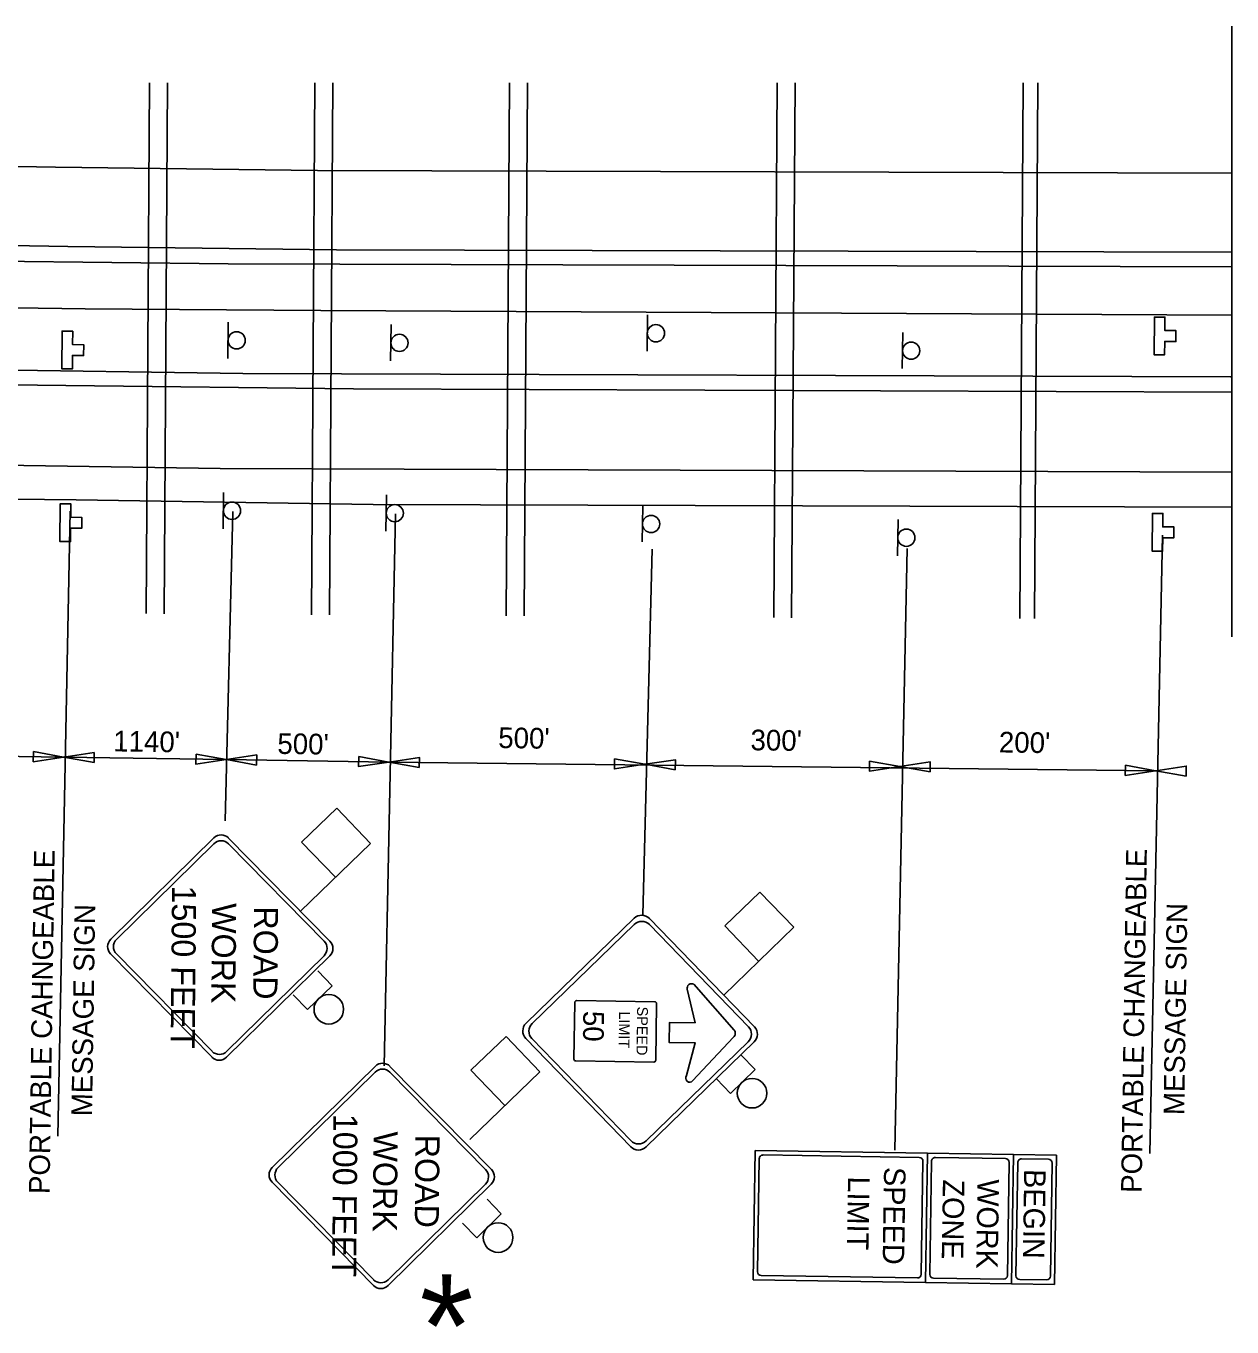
# Model space of a CAD drawing. Extents: x 2155255 to 2162649, y 140388 to 141878.
# Drawn here: x 2158635.8 to 2158985.8, y 141223.4 to 141600.8 of the extents above; entities that cross this region are included whole.
import ezdxf

# ---------------------------------------------------------------- set-up
doc = ezdxf.new("R2010")
doc.units = 0
for name, color, linetype in [('5', 7, 'Continuous'), ('Default', 7, 'Continuous'), ('PR_Dimensions', 7, 'Continuous'), ('PR_Dimensions_Phase4', 7, 'Continuous'), ('PR_Traffic_Control_Devices_Temp', 7, 'Continuous'), ('PR_Traffic_Control_Devices_Temp_Ph4', 7, 'Continuous'), ('SHT_Match_Lines', 7, 'Continuous'), ('T_PHASE_4', 7, 'Continuous'), ('TOPO_Asphalt', 7, 'Continuous')]:
    doc.layers.add(name, color=color, linetype=linetype)

# ---------------------------------------------------------------- blocks, each defined once
blk = doc.blocks.new('Arrowhd')
at = {"layer": 'Default'}
blk.add_lwpolyline([(0.318, -0.053), (0.318, 0.053), (0, 0)], close=True, dxfattribs=at)
blk = doc.blocks.new('PR-TCSIGN')
at = {"layer": 'Default'}
blk.add_line((17.8, 8.5), (-17.8, 8.5), dxfattribs=at)
blk.add_circle((0, 0), 8.47, dxfattribs=at)
blk = doc.blocks.new('FLSHFLAG')
at = {"layer": 'Default'}
for p, q in [((-1.202, 14.125), (0.838, 16.147)), ((0.838, 16.147), (4.9, 12.085)), ((0.819, 12.085), (-1.202, 14.125)), ((0.819, 12.085), (2.86, 14.106)), ((9.258, 14.004), (8.403, 13.149)), ((9.258, 14.004), (10.685, 12.576)), ((10.685, 12.576), (9.831, 11.722))]:
    blk.add_line(p, q, dxfattribs=at)
blk.add_circle((10.653, 13.836), 0.873, dxfattribs=at)
blk = doc.blocks.new('CS-13E')
at = {"layer": 'Default'}
for p, q in [((0, 2.54), (0, 0)), ((7.62, 2.54), (0, 2.54)), ((7.62, 0), (7.62, 2.54)), ((0.254, 2.064), (0.254, 0.476)), ((7.144, 2.286), (0.476, 2.286)), ((7.366, 0.476), (7.366, 2.064)), ((7.62, 0), (0, 0)), ((0.476, 0.254), (7.144, 0.254))]:
    blk.add_line(p, q, dxfattribs=at)
for centre, start, end in [((0.476, 2.064), 90, 180), ((7.144, 2.064), 0, 90), ((0.476, 0.476), 180, 270), ((7.144, 0.476), 270, 0)]:
    blk.add_arc(centre, 0.222, start, end, dxfattribs=at)
blk.add_text('BEGIN', height=1.27, dxfattribs=at).set_placement((0.847, 0.644))
blk = doc.blocks.new('R2-1E_2')
at = {"layer": 'Default'}
for p, q in [((7.62, 10.16), (0, 10.16)), ((0, 10.16), (0, 0)), ((7.62, 0), (7.62, 10.16)), ((0.254, 9.684), (0.254, 0.476)), ((7.144, 9.906), (0.476, 9.906)), ((7.366, 0.476), (7.366, 9.684)), ((0, 0), (7.62, 0)), ((0.476, 0.254), (7.144, 0.254))]:
    blk.add_line(p, q, dxfattribs=at)
for centre, start, end in [((0.476, 9.684), 90, 180), ((7.144, 9.684), 0, 90), ((0.476, 0.476), 180, 270), ((7.144, 0.476), 270, 0)]:
    blk.add_arc(centre, 0.222, start, end, dxfattribs=at)
for s, p in [('SPEED', (0.847, 7.62)), ('LIMIT', (1.439, 5.503))]:
    blk.add_text(s, height=1.27, dxfattribs=at).set_placement(p)
blk = doc.blocks.new('CS-14E')
at = {"layer": 'Default'}
for p, q in [((7.62, 2.54), (0, 2.54)), ((0, 2.54), (0, -2.54)), ((7.62, -2.54), (7.62, 2.54)), ((0.254, 2.064), (0.254, -2.064)), ((7.144, 2.286), (0.476, 2.286)), ((7.366, -2.064), (7.366, 2.064)), ((0.476, -2.286), (7.144, -2.286)), ((7.62, -2.54), (0, -2.54))]:
    blk.add_line(p, q, dxfattribs=at)
for centre, start, end in [((0.476, 2.064), 90, 180), ((7.144, 2.064), 0, 90), ((0.476, -2.064), 180, 270), ((7.144, -2.064), 270, 0)]:
    blk.add_arc(centre, 0.222, start, end, dxfattribs=at)
for s, p in [('WORK', (1.482, 0.444)), ('ZONE', (1.526, -1.598))]:
    blk.add_text(s, height=1.27, dxfattribs=at).set_placement(p)
blk = doc.blocks.new('W3-5_2')
at = {"layer": '5'}
for p, q in [((0.808, 7.633), (6.735, 13.56)), ((13.56, 7.633), (7.633, 13.56)), ((6.735, 0.808), (0.808, 6.735)), ((7.633, 0.808), (13.56, 6.735))]:
    blk.add_line(p, q, dxfattribs=at)
for centre, start, end in [((7.184, 13.111), 45, 135), ((1.257, 7.184), 135, 225), ((13.111, 7.184), 315, 45), ((7.184, 1.257), 225, 315)]:
    blk.add_arc(centre, 0.635, start, end, dxfattribs=at)
at = {"layer": 'Default'}
for p, q in [((0.448, 7.633), (6.735, 13.919)), ((13.919, 7.633), (7.633, 13.919)), ((6.95, 12.723), (4.277, 10.304)), ((9.984, 10.322), (7.366, 12.687)), ((5.352, 8.019), (5.352, 3.415)), ((8.797, 8.13), (5.464, 8.13)), ((8.908, 3.415), (8.908, 8.019)), ((6.735, 0.449), (0.448, 6.735)), ((7.633, 0.449), (13.919, 6.735)), ((5.464, 3.304), (8.797, 3.304))]:
    blk.add_line(p, q, dxfattribs=at)
for points in [[(4.277, 10.304), (6.95, 12.723)], [(7.366, 12.687), (9.984, 10.322)], [(4.584, 9.924), (6.553, 10.412), (6.553, 8.913), (7.745, 8.913), (7.745, 10.448), (9.677, 9.96)], [(9.677, 9.96), (7.745, 10.448), (7.745, 8.913), (6.553, 8.913), (6.553, 10.412), (4.584, 9.924)]]:
    blk.add_lwpolyline(points, dxfattribs=at)
for centre, radius, start, end in [((7.184, 13.47), 0.635, 45, 135), ((7.141, 12.512), 0.285, 37.91416, 132.14933), ((7.141, 12.512), 0.285, 37.91416, 132.14933), ((4.519, 10.186), 0.269, 154.09026, 283.9085), ((4.519, 10.186), 0.269, 154.09026, 283.9085), ((9.825, 10.146), 0.237, 231.34169, 47.91235), ((9.825, 10.146), 0.237, 231.34169, 47.91235), ((5.464, 8.019), 0.111, 90, 180), ((8.797, 8.019), 0.111, 0, 90), ((0.897, 7.184), 0.635, 135, 225), ((13.47, 7.184), 0.635, 315, 45), ((5.464, 3.415), 0.111, 180, 270), ((8.797, 3.415), 0.111, 270, 0), ((7.184, 0.898), 0.635, 225, 315)]:
    blk.add_arc(centre, radius, start, end, dxfattribs=at)
for s, p in [('SPEED', (5.649, 6.987)), ('LIMIT', (5.945, 5.929))]:
    blk.add_text(s, height=0.635, dxfattribs=at).set_placement(p)
blk = doc.blocks.new('Cw20-1_none')
at = {"layer": 'Default'}
for p, q in [((0.177, 3.005), (2.651, 5.48)), ((5.48, 3.005), (3.005, 5.48)), ((0.318, 3.005), (2.651, 5.339)), ((5.338, 3.005), (3.005, 5.339)), ((2.651, 0.177), (0.177, 2.652)), ((2.651, 0.318), (0.318, 2.652)), ((3.005, 0.177), (5.48, 2.652)), ((3.005, 0.318), (5.338, 2.652))]:
    blk.add_line(p, q, dxfattribs=at)
for centre, start, end in [((2.828, 5.303), 45, 135), ((2.828, 5.162), 45, 135), ((0.353, 2.828), 135, 225), ((0.495, 2.828), 135, 225), ((5.162, 2.828), 315, 45), ((5.303, 2.828), 315, 45), ((2.828, 0.495), 225, 315), ((2.828, 0.354), 225, 315)]:
    blk.add_arc(centre, 0.25, start, end, dxfattribs=at)
for s, p in [('ROAD', (1.821, 3.637)), ('WORK', (1.751, 2.623))]:
    blk.add_text(s, height=0.5833, dxfattribs=at).set_placement(p)
blk = doc.blocks.new('PR-TCSIGN_rev')
at = {"layer": 'Default'}
blk.add_lwpolyline([(-5.47, 0), (-1.58, 0), (-1.58, -3.22), (1.58, -3.22), (1.58, 0), (5.47, 0), (5.47, 3.06), (-5.47, 3.06)], close=True, dxfattribs=at)
blk.add_lwpolyline([(1.58, 0), (5.47, 0), (5.47, 3.06), (-5.47, 3.06), (-5.47, 0), (-1.58, 0), (-1.58, -3.22), (1.58, -3.22), (1.58, 0)], dxfattribs=at)

msp = doc.modelspace()

# ---------------------------------------------------------------- linework, layer by layer
at = {"layer": 'PR_Dimensions'}
for p, q in [((2158670.7, 141430.34), (2158671.68, 141584.38)), ((2158675.87, 141430.31), (2158676.86, 141584.38)), ((2158718.67, 141430.03), (2158719.66, 141584.38)), ((2158723.84, 141430), (2158724.83, 141584.38)), ((2158775.17, 141429.69), (2158776.15, 141584.38)), ((2158780.34, 141429.66), (2158781.33, 141584.38)), ((2158852.82, 141429.17), (2158853.8, 141584.38)), ((2158857.99, 141429.14), (2158858.98, 141584.38)), ((2158924.16, 141428.95), (2158925.15, 141584.38)), ((2158928.46, 141428.92), (2158929.45, 141584.38))]:
    msp.add_line(p, q, dxfattribs=at)
at = {"layer": 'PR_Dimensions_Phase4'}
for p, q in [((2158648.64, 141460.09), (2158645.03, 141278.7)), ((2158695.84, 141459.96), (2158693.62, 141370.21)), ((2158743.04, 141459.29), (2158739.75, 141299.17)), ((2158965.56, 141453.11), (2158961.92, 141273.68)), ((2158817.52, 141449.07), (2158814.79, 141342.92)), ((2158891.52, 141449.21), (2158887.93, 141274.62)), ((2158646.69, 141388.69), (2158596.7, 141389.45)), ((2158693.89, 141387.98), (2158646.69, 141388.69)), ((2158741.09, 141387.26), (2158693.89, 141387.98)), ((2158963.6, 141384.74), (2158741.09, 141387.26))]:
    msp.add_line(p, q, dxfattribs=at)
at = {"layer": 'SHT_Match_Lines'}
msp.add_line((2158985.77, 141600.83), (2158985.77, 141423.57), dxfattribs=at)
at = {"layer": 'TOPO_Asphalt'}
for points in [[(2158312.89, 141564.78), (2158365.75, 141563.86), (2158434.03, 141563.05), (2158497.94, 141562.28), (2158572.06, 141561.12), (2158644.35, 141559.9), (2158720.43, 141558.92), (2158985.77, 141558.17)], [(2158985.77, 141535.17), (2158725.88, 141535.87), (2158647.89, 141536.9), (2158575.8, 141538.08), (2158497.77, 141539.11), (2158421.43, 141539.85), (2158349.81, 141540.9), (2158330.84, 141541.37)], [(2158331.86, 141535.76), (2158406.77, 141535.3), (2158478.6, 141534.17), (2158552.92, 141533.47), (2158626.87, 141532.59), (2158694.45, 141531.81), (2158985.77, 141530.96)], [(2158985.77, 141516.93), (2158721.31, 141518.29), (2158652.98, 141518.78), (2158578.1, 141519.84), (2158501.48, 141521.01), (2158428.81, 141521.5), (2158353.61, 141522.5), (2158306.39, 141523.33)], [(2158985.77, 141499), (2158985.31, 141499), (2158698.69, 141500), (2158619.19, 141501.16), (2158547.58, 141501.76), (2158475.74, 141502.47), (2158395.23, 141504.06), (2158326.18, 141505.05)], [(2158330.84, 141500.56), (2158402.62, 141499.42), (2158484.94, 141498.5), (2158565.02, 141497.54), (2158647.34, 141496.57), (2158730.79, 141495.58), (2158985.77, 141494.57)], [(2158985.77, 141471.36), (2158692.13, 141472.41), (2158609.72, 141473.71), (2158521.58, 141474.42), (2158439.64, 141475.58), (2158357.5, 141476.78), (2158315.95, 141477.54)], [(2158321.4, 141466.21), (2158396.62, 141466.56), (2158476.66, 141465.22), (2158567.91, 141464.22), (2158650.39, 141463.34), (2158736.53, 141462.03), (2158985.77, 141461.2)]]:
    msp.add_lwpolyline(points, dxfattribs=at)

# ---------------------------------------------------------------- block references
at = {"layer": 'PR_Dimensions_Phase4'}
for p, xscale, yscale, rotation in [((2158646.69, 141388.69), 27.559000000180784, 27.559000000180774, 179.13349016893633), ((2158646.79, 141388.7), 27.559000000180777, 27.55900000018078, -0.8665098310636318), ((2158693.89, 141387.98), 27.559000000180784, 27.559000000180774, 179.13349016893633), ((2158693.98, 141387.99), 27.559000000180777, 27.55900000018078, -0.8665098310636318), ((2158741.09, 141387.26), 27.559000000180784, 27.559000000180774, 179.13349016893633), ((2158741.18, 141387.28), 27.559000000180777, 27.55900000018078, -0.8665098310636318), ((2158815.36, 141386.61), 27.559000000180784, 27.559000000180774, 179.13349016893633), ((2158815.46, 141386.63), 27.559000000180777, 27.55900000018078, -0.8665098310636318), ((2158889.34, 141385.96), 27.559000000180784, 27.559000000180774, 179.13349016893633), ((2158889.43, 141385.98), 27.559000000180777, 27.55900000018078, -0.8665098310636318), ((2158963.6, 141384.74), 27.559000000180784, 27.559000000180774, 179.13349016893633), ((2158963.7, 141384.75), 27.558999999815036, 27.55899999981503, -0.8665098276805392), ((2158963.7, 141384.75), 27.559000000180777, 27.55900000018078, -0.8665098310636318)]:
    msp.add_blockref('Arrowhd', p, dxfattribs=dict(at, xscale=xscale, yscale=yscale, rotation=rotation))
at = {"layer": 'PR_Traffic_Control_Devices_Temp_Ph4'}
for name, p, xscale, yscale, rotation in [('PR-TCSIGN', (2158818.6, 141511.69), 0.29527500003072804, 0.2952750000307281, 89.1334901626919), ('PR-TCSIGN', (2158696.92, 141509.62), 0.29527500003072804, 0.2952750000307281, 89.1334901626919), ('PR-TCSIGN', (2158744.17, 141508.9), 0.29527500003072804, 0.2952750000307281, 89.1334901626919), ('PR-TCSIGN', (2158892.67, 141506.63), 0.29527500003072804, 0.2952750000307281, 89.1334901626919), ('PR-TCSIGN', (2158695.58, 141460.19), 0.29527500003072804, 0.2952750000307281, 89.1334901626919), ('PR-TCSIGN', (2158742.82, 141459.48), 0.29527500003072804, 0.2952750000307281, 89.1334901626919), ('PR-TCSIGN', (2158817.2, 141456.35), 0.29527500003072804, 0.2952750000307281, 89.1334901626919), ('PR-TCSIGN', (2158891.28, 141452.36), 0.29527500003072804, 0.2952750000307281, 89.1334901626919), ('FLSHFLAG', (2158656.38, 141368.98), 4.92125000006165, 4.92125000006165, -90.8665098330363), ('Cw20-1_none', (2158658.53, 141367.67), 12, 12, -90.5014925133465), ('FLSHFLAG', (2158779.2, 141344.64), 4.92125000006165, 4.92125000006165, -90.8665098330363), ('W3-5_2', (2158779.2, 141344.64), 4.92125000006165, 4.92125000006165, -90.8665098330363), ('FLSHFLAG', (2158705.51, 141302.75), 4.92125000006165, 4.92125000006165, -90.8665098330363), ('Cw20-1_none', (2158705.38, 141301.42), 12, 12, -90.5014925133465), ('R2-1E_2', (2158847.38, 141274.54), 4.92125000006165, 4.92125000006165, -90.8665098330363), ('CS-14E', (2158909.87, 141273.6), 4.921249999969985, 4.9212499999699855, -90.8665098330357), ('CS-13E', (2158922.37, 141273.41), 4.92124999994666, 4.921249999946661, -90.86650984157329)]:
    msp.add_blockref(name, p, dxfattribs=dict(at, xscale=xscale, yscale=yscale, rotation=rotation))
at = {"layer": 'PR_Traffic_Control_Devices_Temp_Ph4', "rotation": 89.4985074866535}
for p in [(2158966.28, 141510.9), (2158649.3, 141506.82), (2158648.76, 141456.7), (2158965.68, 141453.92)]:
    msp.add_blockref('PR-TCSIGN_rev', p, dxfattribs=at)

# ---------------------------------------------------------------- texts
at = {"layer": 'PR_Traffic_Control_Devices_Temp'}
msp.add_text('*', height=30, dxfattribs=at).set_placement((2158750.02, 141208.66))
at = {"layer": 'PR_Traffic_Control_Devices_Temp_Ph4'}
for s, height, p in [('1500 FEET', 7, (2158678.18, 141351.48)), ('50', 6, (2158797.52, 141315.09)), ('1000 FEET', 7, (2158725.02, 141285.23))]:
    msp.add_text(s, height=height, rotation=269.4985, dxfattribs=at).set_placement(p)
at = {"layer": 'T_PHASE_4'}
for s, rotation, p in [("1140'", 359.1335, (2158661.07, 141390.37)), ("500'", 359.1335, (2158708.71, 141389.65)), ("500'", 359.1335, (2158772.81, 141391.34)), ("300'", 359.1335, (2158846.01, 141390.7)), ("200'", 359.1335, (2158918.09, 141390.07)), ('PORTABLE CAHNGEABLE', 89.1335, (2158642.62, 141261.89)), ('PORTABLE CHANGEABLE', 89.1335, (2158959.57, 141262.23)), ('MESSAGE SIGN', 89.1335, (2158654.96, 141284.46)), ('MESSAGE SIGN', 89.1335, (2158971.91, 141284.8))]:
    msp.add_text(s, height=6, rotation=rotation, dxfattribs=at).set_placement(p)

doc.saveas('drawing.dxf')
